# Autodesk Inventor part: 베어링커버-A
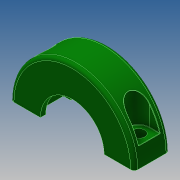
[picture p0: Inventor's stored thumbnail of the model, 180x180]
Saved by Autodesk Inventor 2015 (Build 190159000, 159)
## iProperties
Created: 2018-01
Part Number: 베어링커버-A
Material: 알루미늄 6061
Document SubType Name: Modeling
Designer: mduedu
Density: 2.71 g/cm^3
Appearance: 진녹색
Mass: 7.21302 g
Surface Area: 19.9383 cm^2
Volume: 2.66163 cm^3
Author: mduedu
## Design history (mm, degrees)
sketch "스케치1"
  geometry: L1 (-17.5, 0)-(17.5, 0); A1 r 17.5 centre (0, 0) between (-17.5, 0) and (17.5, 0); 2 further points
  constraints: 2 coincident, 2 end point, 2 point on circle, 1 centre point, 1 horizontal, 1 midpoint
  dimensions: "d0" = 35 diameter of A1
extrude "돌출1" new body sketch "스케치1" stored distance "d1" = 10; taper "d2" = 0 deg
sketch "스케치2"
  geometry: C1 r 11 at (0, 0); C2 r 9 at (0, 0); 1 further point
  constraints: 2 centre point, 2 coincident
  dimensions: "d3" = 22 diameter of C1; "d4" = 18 diameter of C2
extrude "돌출2" cut sketch "스케치2" stored distance "d5" = 7; taper "d6" = 0 deg
extrude "돌출3" cut sketch "스케치2" stored distance "d7" = 7; taper "d8" = 0 deg
fillet "모깎기1" dims "d9" = 0.3
fillet "모깎기2" dims "d10" = 1
node "작업 평면1"
sketch "스케치3"
  geometry: L1 (-15.5, -3.5)-(33.5, -3.5) reference; L2 (-4.771, -6.5)-(-7.771, -6.5); L3 (-7.771, -6.5)-(-7.771, -0.5); L4 (-7.771, -0.5)-(-4.771, -0.5); L5 (-0.46, -7)-(1.517, -7) reference; L6 (1.517, -7)-(1.517, -8.5) reference; L7 (1.517, -8.5)-(-6.724, -8.5) reference; L8 (-7.771, -7.5)-(-7.771, 0.5) reference; L9 (-6.724, 1.5)-(1.517, 1.5) reference; L10 (1.517, 1.5)-(1.517, 0) reference; L11 (1.517, 0)-(-0.46, 0) reference; L12 (-0.798, -0.3)-(-0.798, -6.7) reference; L13 (18.798, -6.7)-(18.798, -0.3) reference; L14 (18.46, 0)-(16.483, 0) reference; L15 (16.483, 0)-(16.483, 1.5) reference; L16 (16.483, 1.5)-(24.724, 1.5) reference; L17 (25.771, 0.5)-(25.771, -7.5) reference; L18 (24.724, -8.5)-(16.483, -8.5) reference; L19 (16.483, -8.5)-(16.483, -7) reference; L20 (16.483, -7)-(18.46, -7) reference; A1 r 3 centre (-4.771, -3.5) between (-4.771, -6.5) and (-4.771, -0.5); 1 further point
  constraints: 6 end point, 2 point on circle, 2 tangent, 1 centre point, 1 collinear, 1 horizontal, 1 parallel, 1 perpendicular, 1 point on line, 8 other
  dimensions: "d12" = 6 distance between parallel lines of L4 L2; "d14" = 6 dimension on A1 L3
extrude "돌출4" cut sketch "스케치3" stored distance "d15" = 0; taper "d16" = 0 deg
sketch "스케치4"
  geometry: 7 further points
  constraints: 4 vertical alignment, 2 horizontal alignment
sketch "스케치5"
  geometry: 2 further points
  constraints: 2 other
hole "구멍1" sketch "스케치5" at (-22.771, 3.5), (4.771, 3.5) diameter "d17" = 3.4; stored, may be unused: countersink angle "d21" = 90 deg, drill point angle "d23" = 0 deg; dims "d18" = 6, "d19" = 4, "d20" = 2, "d22" = 8
fillet "모깎기3" dims "d24" = 0.1
node "솔리드1"
mirror "대칭1"
node "절단 모서리 투영1"
other parameters: "d11" = -5
